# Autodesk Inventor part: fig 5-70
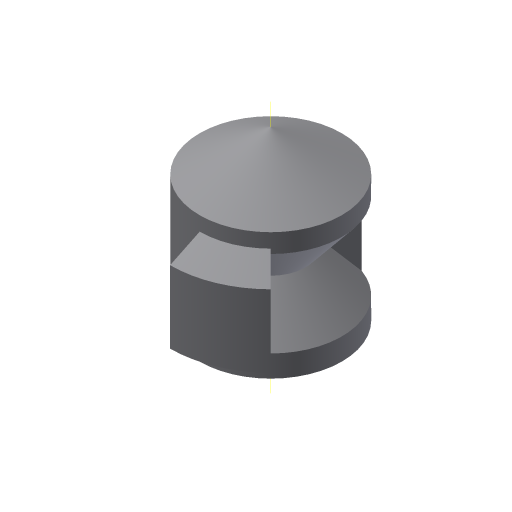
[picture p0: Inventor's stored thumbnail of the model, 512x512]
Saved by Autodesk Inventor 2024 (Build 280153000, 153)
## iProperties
Created: 2004-05
Part Number: fig 5-70
Document SubType Name: Modeling
Designer: CADCIM Technologies
Manufacturer: Standard
Standards Organization: Custom
Density: 1 g/cm^3
Material: Generic
Appearance: Default
Author: CADCIM Technologies
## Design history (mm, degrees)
sketch "Sketch1"
  geometry: L1 (0, -21.51)-(0, 21.51); L2 (0, 21.51)-(-14.639, 13.059); L3 (-14.639, 13.059)-(-14.639, -13.059); L4 (-14.639, -13.059)-(0, -21.51); 2 further points
  constraints: 8 end point, 1 coincident, 1 equal length, 1 midpoint, 1 parallel, 1 vertical, 1 other
  dimensions: "d3" = 120 deg angle of L4 L3
revolve "Revolution1" sketch "Sketch1" stored, may be unused: angle "d0" = 90 deg
workaxis "Work Axis1"
sketch "Sketch2"
  geometry: L1 (-15.658, 10.423)-(-7.144, 0); L2 (-7.144, 0)-(-15.658, -9.738); L3 (-15.658, -9.738)-(-15.658, 10.423); L4 (0, -25.812)-(0, 34.416) reference
  constraints: 6 end point, 1 vertical
revolve "Revolution2" sketch "Sketch2" stored, may be unused: angle "d4" = 140 deg
sketch "Sketch3"
  geometry: L1 (-14.955, 9.983)-(-20.736, 7.191); L2 (-20.736, 7.191)-(-20.736, -7.686); L3 (-20.736, -7.686)-(-15, -10.57); L4 (0, -25.812)-(0, 34.416) reference
  constraints: 6 end point, 1 equal length, 1 vertical
revolve "Revolution4" sketch "Sketch3" stored, may be unused: angle "d9" = 45 deg
body "Solid1"
other parameters: "d11" = 45 deg
